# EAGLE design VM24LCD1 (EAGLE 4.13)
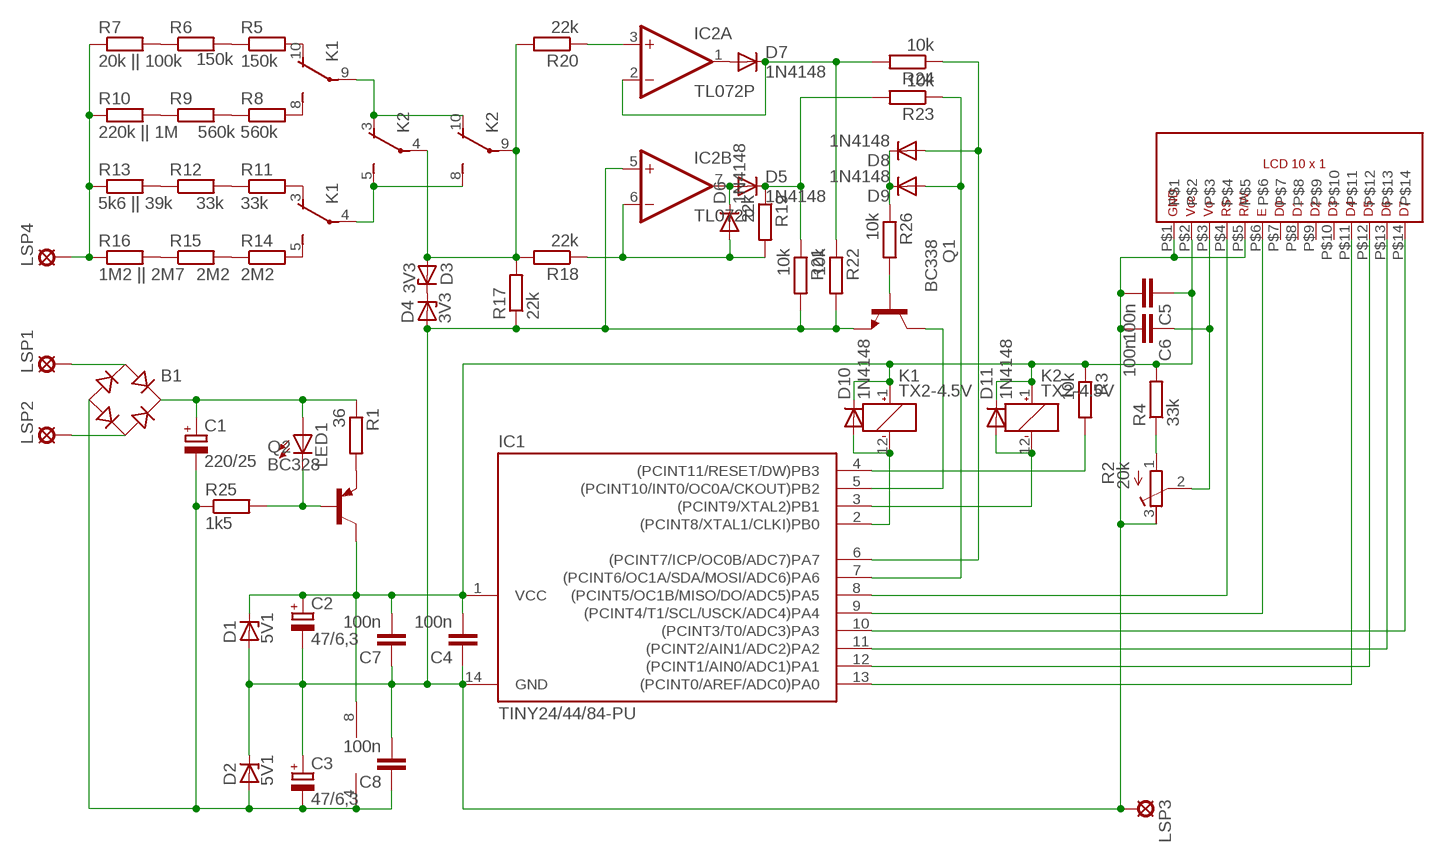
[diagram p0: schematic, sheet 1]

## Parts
B1  B-DIL  [B-DIL]
C1  220/25  CPOL-EUE5-6  [E5-6]
C2  47/6,3  CPOL-EUE5-6  [E5-6]
C3  47/6,3  CPOL-EUE5-6  [E5-6]
C4  100n  C-EUC1206  [C1206]
C5  100n  C-EUC0805K  [C0805K]
C6  100n  C-EUC0805K  [C0805K]
C7  100n  C-EUC1206  [C1206]
C8  100n  C-EUC1206  [C1206]
D1  5V1  ZENER-DIODESMB  [SMB]
D2  5V1  ZENER-DIODESMB  [SMB]
D3  3V3  ZENER-DIODEZD-2.5  [ZDIO-2.5]
D4  3V3  ZENER-DIODEZD-2.5  [ZDIO-2.5]
D5  1N4148  DIODE-D-2.5  [D-2.5]
D6  1N4148  DIODE-D-2.5  [D-2.5]
D7  1N4148  DIODE-D-2.5  [D-2.5]
D8  1N4148  DIODE-D-2.5  [D-2.5]
D9  1N4148  DIODE-D-5  [D-5]
D10  1N4148  DIODE-MINIMELF  [MINIMELF]
D11  1N4148  DIODE-MINIMELF  [MINIMELF]
IC1  TINY24/44/84-PU  [DIL14]
IC2  TL072P  [DIL08]
K1  TX2-4.5V  [TX2]
K2  TX2-4.5V  [TX2]
LED1  LEDSMT1206  [1206]
LSP1  LSP10  [LSP10]
LSP2  LSP10  [LSP10]
LSP3  LSP10  [LSP10]
LSP4  LSP10  [LSP10]
Q1  BC338  [TO92-EBC]
Q2  BC328  [TO92-EBC]
R1  36  R-EU_0207/10  [0207/10]
R2  20k  R-TRIMM4G/J  [RTRIM4G/J]
R3  10k  R-EU_M0805  [M0805]
R4  33k  R-EU_M0805  [M0805]
R5  150k  R-EU_0207/10  [0207/10]
R6  150k  R-EU_0207/10  [0207/10]
R7  20k || 100k  R-EU_0207/10  [0207/10]
R8  560k  R-EU_0207/10  [0207/10]
R9  560k  R-EU_0207/10  [0207/10]
R10  220k || 1M  R-EU_0207/10  [0207/10]
R11  33k  R-EU_0207/10  [0207/10]
R12  33k  R-EU_0207/10  [0207/10]
R13  5k6 || 39k  R-EU_0207/10  [0207/10]
R14  2M2  R-EU_0207/10  [0207/10]
R15  2M2  R-EU_0207/10  [0207/10]
R16  1M2 || 2M7  R-EU_0207/10  [0207/10]
R17  22k  R-EU_0204/7  [0204/7]
R18  22k  R-EU_0204/7  [0204/7]
R19  22k  R-EU_0204/5  [0204/5]
R20  22k  R-EU_0204/7  [0204/7]
R21  10k  R-EU_M0805  [M0805]
R22  10k  R-EU_M0805  [M0805]
R23  10k  R-EU_0204/7  [0204/7]
R24  10k  R-EU_0204/5  [0204/5]
R25  1k5  R-EU_MELF0204W  [MINI_MELF-0204W]
R26  10k  R-EU_MELF0102W  [MINI_MELF-0102W]
U$1  LCD10X1P  [LCD10X1P]

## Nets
N$1: B1.+ C1.+ LED1.A R1.1
N$2: C2.+ C4.2 C5.1 C7.2 D1.C D10.C D11.C IC1.1(VCC) IC2.8(P:V+) K1.1(_:+) K2.1(_:+) Q2.C R3.1 R4.2 U$1.P$2
N$3: C2.- C3.+ C4.1 C5.2 C6.2 C7.1 C8.2 D1.A D2.C D4.A IC1.14(GND) IC2.5(B:+IN) LSP3.MP Q1.E R2.3(A) R17.1 R21.2 R22.2 U$1.P$1 U$1.P$5
N$4: B1.- C1.- C3.- C8.1 D2.A IC2.4(P:V-) R25.1
N$5: IC1.10((PCINT3/T0/ADC3)PA3) U$1.P$14
N$6: IC1.11((PCINT2/AIN1/ADC2)PA2) U$1.P$13
N$7: IC1.12((PCINT1/AIN0/ADC1)PA1) U$1.P$12
N$8: IC1.13((PCINT0/AREF/ADC0)PA0) U$1.P$11
N$9: IC1.9((PCINT4/T1/SCL/USCK/ADC4)PA4) U$1.P$6
N$10: IC1.8((PCINT5/OC1B/MISO/DO/ADC5)PA5) U$1.P$4
N$11: R2.1(E) R4.1
N$12: C6.1 R2.2(S) U$1.P$3
N$13: D10.A IC1.2((PCINT8/XTAL1/CLKI)PB0) K1.12(_:-)
N$14: IC1.4((PCINT11/RESET/DW)PB3) R3.2
N$15: D11.A IC1.3((PCINT9/XTAL2)PB1) K2.12(_:-)
N$16: D3.A K2.4(1:P) K2.9(2:P) R17.2 R18.2 R20.2
N$17: K1.4(1:P) K2.5(1:S) K2.8(2:S)
N$18: K1.9(2:P) K2.3(1:O) K2.10(2:O)
N$19: K1.10(2:O) R5.2
N$20: R5.1 R6.2
N$21: R6.1 R7.2
N$22: K1.8(2:S) R8.2
N$23: R8.1 R9.2
N$24: R9.1 R10.2
N$25: K1.3(1:O) R11.2
N$26: R11.1 R12.2
N$27: R12.1 R13.2
N$28: K1.5(1:S) R14.2
N$29: R14.1 R15.2
N$30: R15.1 R16.2
N$31: LSP4.MP R7.1 R10.1 R13.1 R16.1
N$40: D3.C D4.C
N$41: D5.A D6.C IC2.7(B:OUT)
N$42: D7.A IC2.1(A:OUT)
N$43: D5.C R19.1 R21.1 R23.2
N$44: D6.A IC2.6(B:-IN) R18.1 R19.2
N$45: B1.AC1 LSP1.MP
N$46: IC2.3(A:+IN) R20.1
N$47: D7.C IC2.2(A:-IN) R22.1 R24.2
N$48: IC1.5((PCINT10/INT0/OC0A/CKOUT)PB2) Q1.C
N$49: D8.C D9.C R26.1
N$50: D8.A IC1.6((PCINT7/ICP/OC0B/ADC7)PA7) R24.1
N$51: D9.A IC1.7((PCINT6/OC1A/SDA/MOSI/ADC6)PA6) R23.1
N$52: B1.AC2 LSP2.MP
N$61: Q2.E R1.2
N$62: LED1.C Q2.B R25.2
N$66: Q1.B R26.2
Unconnected: U$1.P$7 U$1.P$8 U$1.P$9 U$1.P$10

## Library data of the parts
B1 = rectifier:B-DIL: RECTIFIER
C1-C3 = rcl:CPOL-EU: POLARIZED CAPACITOR, European symbol
C4-C8 = rcl:C-EU: CAPACITOR, European symbol
D1-D4 = diode:ZENER-DIODE: Z-Diode
D5-D11 = diode:DIODE-: DIODE
IC1 = avr-4:TINY24/44/84
IC2 = linear:TL072: OP AMP
K1 K2 = relay:TX2?-*: 2 AMP. HIGH CAPACITY RELAY NAiS WITH HIGH SURGE VOLTAGE & HIGH BREAKDOWN VOLTAGE Source: http://www.mew-europe.com/.. en_ds_61022_0001.pdf
LED1 = led:LED: LED
LSP1-LSP4 = solpad:LSP10: SOLDER PAD
Q1 = transistor-npn:BC338*: NPN Transistor
Q2 = transistor-pnp:BC328*: PNP Transistror
R1 R3-R26 = rcl:R-EU_: RESISTOR, European symbol
R2 = rcl:R-TRIMM: Trimm resistor
U$1 = meine:LCD10X1P

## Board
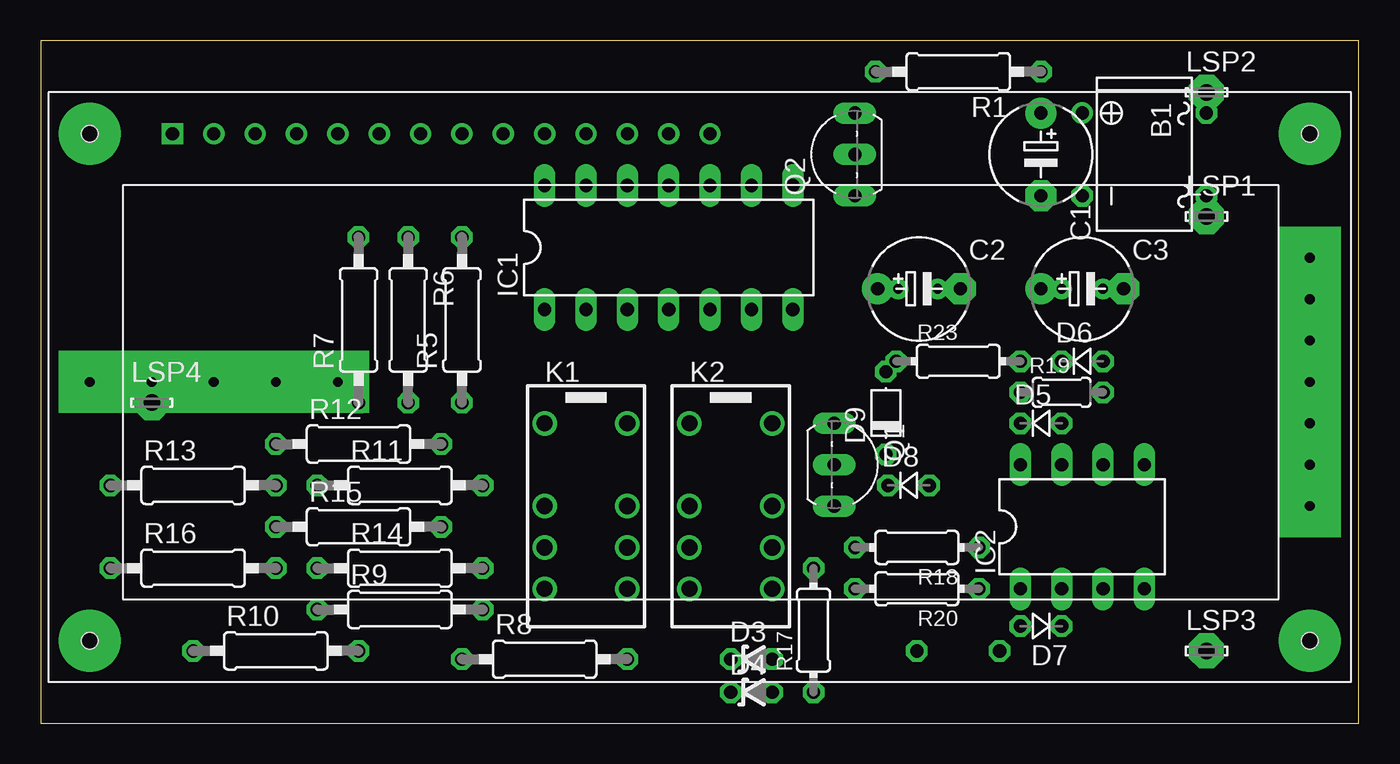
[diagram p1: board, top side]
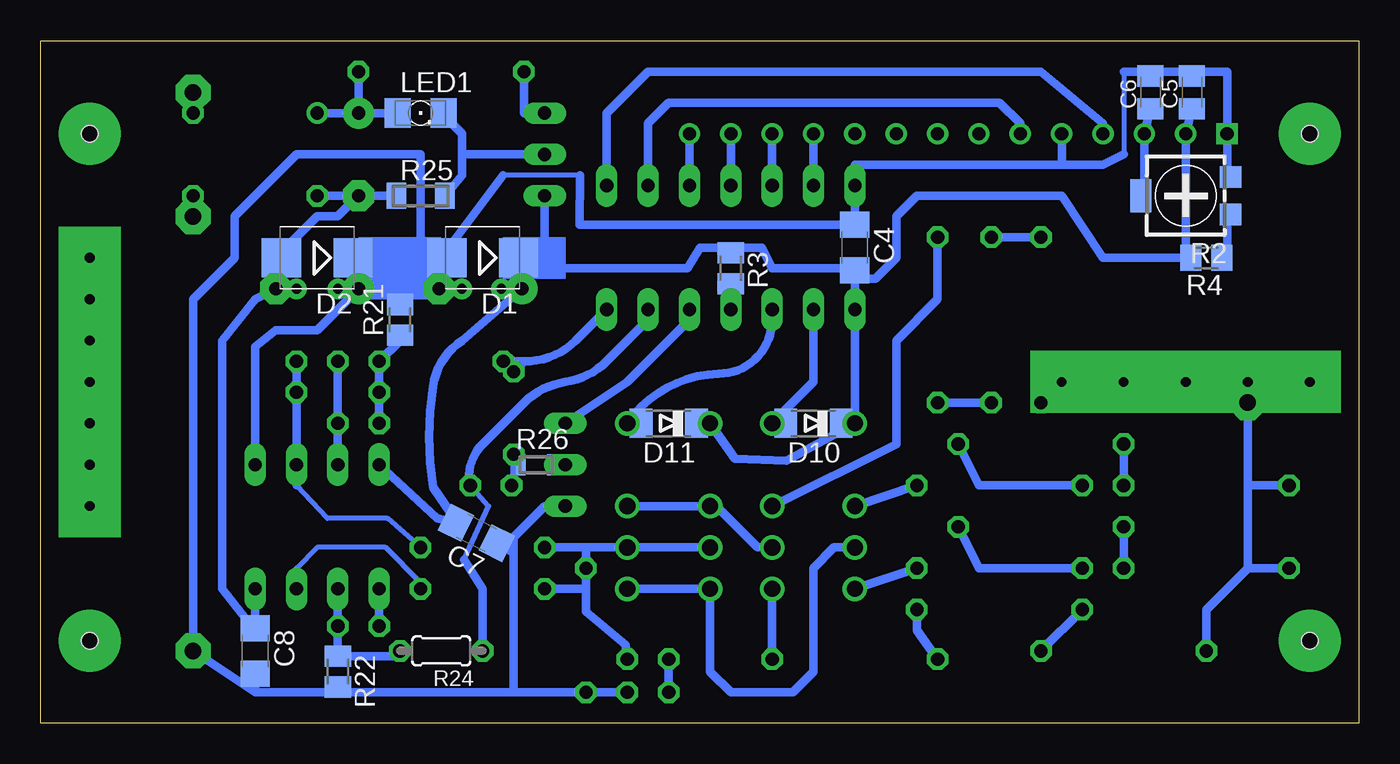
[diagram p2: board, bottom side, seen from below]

Size 80.95 x 41.9 mm. Coordinates in mm from the lower left corner, seen from the top.
Outline: 0,0 80.95,0 80.95,41.9 0,41.9 0,0
Copper layers (1*16): Top 0.035mm / dielectric 1.5mm / Bottom 0.035mm
Design rules "default": minimum track width 10mil, minimum drill 24mil, track to track 8mil, track to pad 8mil, pad to pad 8mil, via to via 8mil, smd to smd 0mil, copper to edge 40mil, drill to drill 8mil, minimum pad ring 10mil, minimum via ring 8mil, stop-mask expansion 4mil, vias tented up to drill 0mil, thermal gap 10mil

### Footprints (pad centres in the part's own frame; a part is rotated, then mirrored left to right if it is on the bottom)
B-DIL = drill 0.813 round: + -2.54,-3.81 | drill 0.813 octagon: - 2.54,-3.81; AC1 2.54,3.81; AC2 -2.54,3.81
E5-6 = drill 0.813 pad 1.905 round: + -2.54,0 | drill 0.813 pad 1.905 octagon: - 2.54,0
C1206 = smd 1.6 x 1.8: 1 -1.4,0; 2 1.4,0
C0805K = smd 1.3 x 1.6: 1 -1,0; 2 1,0
SMB = smd 2.4 x 2.4: A 2.2,0; C -2.2,0
ZDIO-2.5 = drill 0.813 octagon: A 1.27,0; C -1.27,0
D-2.5 = drill 0.813 octagon: A 1.27,0; C -1.27,0
D-5 = drill 0.813 octagon: A 2.54,0; C -2.54,0
MINIMELF = smd 1.4 x 1.8: A 1.7,0; C -1.7,0
DIL14 = drill 0.813 long: 1 -7.62,-3.81; 2 -5.08,-3.81; 3 -2.54,-3.81; 4 0,-3.81; 5 2.54,-3.81; 6 5.08,-3.81; 7 7.62,-3.81; 8 7.62,3.81; 9 5.08,3.81; 10 2.54,3.81; 11 0,3.81; 12 -2.54,3.81; 13 -5.08,3.81; 14 -7.62,3.81
DIL08 = drill 0.813 long: 1 -3.81,-3.81; 2 -1.27,-3.81; 3 1.27,-3.81; 4 3.81,-3.81; 5 3.81,3.81; 6 1.27,3.81; 7 -1.27,3.81; 8 -3.81,3.81
TX2 = drill 1 round: 1 -5.08,-2.54; 3 0,-2.54; 4 2.54,-2.54; 5 5.08,-2.54; 8 5.08,2.54; 9 2.54,2.54; 10 0,2.54; 12 -5.08,2.54
1206 = smd 1.6 x 1.803: A -1.422,0; C 1.422,0
LSP10 = drill 1.016 pad 2.159 octagon: MP 0,0
TO92-EBC = drill 0.813 long: B 0,-1.27; C -2.54,-1.27; E 2.54,-1.27
0207/10 = drill 0.813 octagon: 1 -5.08,0; 2 5.08,0
RTRIM4G/J = smd 1.3 x 1.3: 1 -1.15,-2.75; 3 1.15,-2.75 | smd 2 x 1.3: 2 0,2.75
M0805 = smd 1.3 x 1.6: 1 -0.95,0; 2 0.95,0
0204/7 = drill 0.813 octagon: 1 -3.81,0; 2 3.81,0
0204/5 = drill 0.813 octagon: 1 -2.54,0; 2 2.54,0
MINI_MELF-0204W = smd 1.2 x 1.6: 1 -1.5,0; 2 1.5,0
MINI_MELF-0102W = smd 0.6 x 1.3: 1 -0.95,0; 2 0.95,0
LCD10X1P = drill 0.8 square: P$1 7.62,33.02 | drill 0.8 round: P$2 10.16,33.02; P$3 12.7,33.02; P$4 15.24,33.02; P$5 17.78,33.02; P$6 20.32,33.02; P$7 22.86,33.02; P$8 25.4,33.02; P$9 27.94,33.02; P$10 30.48,33.02; P$11 33.02,33.02; P$12 35.56,33.02; P$13 38.1,33.02; P$14 40.64,33.02 | hole 1: 2.54,1.905; 2.54,33.02; 77.47,33.02; 77.47,1.905

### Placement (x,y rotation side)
B1  67.78,34.92 270 top
C1  61.43,34.92 270 top
C2  53.94,26.66 0 top
C3  63.97,26.66 0 top
C4  30.95,29.2 270 bottom
C5  10.25,38.73 90 bottom
C6  12.79,38.73 90 bottom
C7  54.19,11.68 153.5 bottom
C8  67.78,4.44 270 bottom
D1  53.81,28.57 180 bottom
D2  63.97,28.57 180 bottom
D3  43.65,3.93 0 top
D4  43.65,1.9 0 top
D5  61.43,18.41 0 top
D6  63.97,22.22 0 top
D7  61.43,5.96 180 top
D8  53.3,14.6 0 top
D9  51.91,19.04 90 top
D10  33.49,18.41 180 bottom
D11  42.38,18.41 180 bottom
IC1  38.57,29.2 0 top
IC2  63.97,12.06 0 top
K1  33.49,13.33 270 top
K2  42.38,13.33 270 top
LED1  57.62,37.46 0 bottom
LSP1  71.59,31.11 0 top
LSP2  71.59,38.73 0 top
LSP3  71.59,4.44 0 top
LSP4  6.82,19.68 0 top
Q1  50,15.87 270 top
Q2  48.73,34.92 90 top
R1  56.35,40 180 top
R2  10.63,32.38 90 bottom
R3  38.57,27.93 270 bottom
R4  9.36,28.57 180 bottom
R5  25.87,24.76 90 top
R6  22.57,24.76 270 top
R7  19.52,24.76 90 top
R8  30.95,3.93 0 top
R9  22.06,6.98 0 top
R10  14.44,4.44 0 top
R11  22.06,14.6 0 top
R12  19.52,17.14 0 top
R13  9.36,14.6 0 top
R14  22.06,9.52 0 top
R15  19.52,12.06 0 top
R16  9.36,9.52 0 top
R17  47.46,5.71 90 top
R18  53.81,10.79 180 top
R19  62.7,20.31 0 top
R20  53.81,8.25 180 top
R21  58.89,24.76 90 bottom
R22  62.7,3.17 270 bottom
R23  56.35,22.22 0 top
R24  56.35,4.44 180 bottom
R25  57.62,32.38 0 bottom
R26  50.51,15.87 0 bottom
U$1  0.47,3.17 0 top

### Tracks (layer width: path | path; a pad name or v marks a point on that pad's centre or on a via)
N$1
  Bottom 0.508: C1.+ R1.1 | C1.+ B1.+ | LED1.A C1.+
N$2
  Bottom 0.406: K1.1 D10.C | K2.1 D11.C
  Bottom 0.508: C5.1 U$1.P$2 10.63,28.57 | R4.2 10.63,28.57 | 30.95,27.3 IC1.1 K1.1 35.14,16.12 38.32,16.25 K2.1 | 30.95,27.3 C4.2 30.95,27.93 36.03,27.93 36.66,29.2 38.57,29.2 | 10.63,28.57 15.71,28.57 18.25,32.38 27.14,32.38 28.41,31.11 28.41,28.57 29.68,27.3 30.95,27.3 | 38.57,29.2 40.48,29.2 41.24,27.93 51.4,27.93 | 38.57,29.2 R3.1 | 51.4,27.93 D1.C | 51.4,27.93 51.35,27.29 | 51.35,27.29 C2.+ 55.08,23.49 arc-48 56.86,20.7 arc-17 56.86,14.47 55.44,12.42 C7.2 55.46,12.31 56.6,12.57 IC2.8 | 51.35,27.29 51.28,27.29 50,28.57 Q2.C
N$3
  Bottom 0.305: 14.44,40 14.44,34.92 | 47.84,33.65 52.54,33.65
  Bottom 0.508: 30.95,33.65 30.95,34.29 18.25,34.29 | 30.95,33.65 IC1.14 | 18.25,34.29 U$1.P$5 | 18.25,34.29 15.71,34.29 14.44,34.92 | 10.63,40 8.09,40 U$1.P$1 8.09,33.53 R2.3 | 10.63,40 13.17,40 | 13.17,40 14.44,40 | 10.63,40 C5.2 | 13.17,40 C6.2 | 30.95,33.65 C4.1 47.84,30.61 47.84,33.65 | 52.54,33.65 56.35,28.57 D1.A 55.71,28.57 56.35,27.93 C2.- | D2.C 61.43,28.57 C3.+ | C2.- C3.+ | C3.+ 63.97,24.12 66.51,24.12 67.78,23.11 IC2.5 | C2.- 57.62,29.84 57.62,34.92 65.24,34.92 69.05,31.11 69.05,28.57 71.59,26.03 LSP3.MP 67.78,1.9 | D4.A R17.1 51.91,1.9 | 67.78,1.9 62.7,1.9 | 62.7,1.9 51.91,1.9 | 51.91,1.9 51.91,10.54 | 51.91,10.54 51.91,11.43 50,13.33 Q1.E | 51.91,10.54 52.03,10.54 C7.1 | 67.78,1.9 C8.2 | R21.2 58.89,26.03 58.25,26.66 C2.- | 62.7,1.9 R22.2
N$4
  Bottom 0.508: C1.- B1.- | C1.- 62.7,31.11 63.97,31.11 66.17,28.91 D2.A 66.51,28.57 C3.- 67.78,26.03 69.81,23.49 69.81,8.25 67.91,5.84 C8.1 | C8.1 67.78,5.71 | C8.1 IC2.4 | C1.- R25.1
N$5
  Bottom 0.508: IC1.10 U$1.P$14
N$6
  Bottom 0.508: IC1.11 U$1.P$13
N$7
  Bottom 0.508: IC1.12 U$1.P$12
N$8
  Bottom 0.508: IC1.13 U$1.P$11
N$9
  Bottom 0.508: IC1.9 43.65,36.83 42.38,38.1 22.06,38.1 20.79,36.83 U$1.P$6
N$10
  Bottom 0.508: IC1.8 46.19,37.46 43.65,40 19.52,40 15.71,36.83 U$1.P$4
N$11
  Bottom 0.508: R4.1 8.09,28.57 8.09,31.23 R2.1
N$12
  Bottom 0.508: C6.1 U$1.P$3 13.17,32.38 R2.2
N$13
  Bottom 0.406: D10.A K1.12
  Bottom 0.508: IC1.2 33.49,20.95 K1.12
N$14
  Bottom 0.508: IC1.4 R3.2
N$15
  Bottom 0.406: K2.12 D11.A
  Bottom 0.508: IC1.3 36.03,24.76 arc90 39.33,21.46 arc-53 K2.12
N$16
  Bottom 0.508: K2.4 K2.9 47.46,10.79 | 47.46,8.25 47.46,6.85 45.05,4.82 D3.A | 47.46,8.25 R17.2 47.46,10.79 | 47.46,10.79 R18.2 | 47.46,8.25 R20.2
N$17
  Bottom 0.508: K1.4 32.22,10.79 33.49,9.52 33.49,3.17 34.76,1.9 38.57,1.9 39.84,3.17 K2.5 K2.8
N$18
  Bottom 0.508: K2.10 K2.3 39.46,13.33 36.92,10.79 K1.9
N$19
  Bottom 0.508: K1.10 28.41,17.14 28.41,23.49 25.87,26.03 R5.2
N$20
  Bottom 0.508: R6.2 R5.1
N$21
  Bottom 0.508: R7.2 R6.1
N$22
  Bottom 0.508: R8.2 K1.8
N$23
  Bottom 0.508: R9.2 27.14,5.71 R8.1
N$24
  Bottom 0.508: R10.2 R9.1
N$25
  Bottom 0.508: R11.2 K1.3
N$26
  Bottom 0.508: R11.1 23.33,14.6 R12.2
N$27
  Bottom 0.508: R13.2 R12.1
N$28
  Bottom 0.508: R14.2 K1.5
N$29
  Bottom 0.508: R14.1 23.33,9.52 R15.2
N$30
  Bottom 0.508: R16.2 R15.1
N$31
  Bottom 0.508: R10.1 9.36,6.98 6.82,9.52 | R16.1 6.82,9.52 | R7.1 LSP4.MP 6.82,14.6 | 6.82,9.52 6.82,14.6 | 6.82,14.6 R13.1
N$32  (via drill 0.6 pad 3.81)
  other vias: 6.82,20.95
N$33  (via drill 0.6 pad 3.81)
  other vias: 10.63,20.95
N$34  (via drill 0.6 pad 3.81)
  other vias: 14.44,20.95
N$35  (via drill 0.6 pad 3.81)
  other vias: 18.25,20.95
N$36  (via drill 0.6 pad 3.81)
  other vias: 3.01,36.19
N$37  (via drill 0.6 pad 3.81)
  other vias: 3.01,5.08
N$38  (via drill 0.6 pad 3.81)
  other vias: 77.94,5.08
N$39  (via drill 0.6 pad 3.81)
  other vias: 77.94,36.19
N$40
  Bottom 0.508: D4.C D3.C
N$41
  Bottom 0.508: D6.C D5.A IC2.7
N$42
  Bottom 0.508: D7.A IC2.1
N$43
  Bottom 0.508: D5.C 60.16,20.19 60.29,20.31 R19.1 R23.2 58.89,23.49 R21.1
N$44
  Bottom 0.305: R18.1 59.65,12.57 63.34,12.57 65.24,14.6
  Bottom 0.508: D6.A R19.2 IC2.6 65.24,14.6
N$45
  Bottom 0.508: LSP1.MP B1.AC1
N$46
  Bottom 0.305: R20.1 57.62,8.63 59.78,10.79 63.97,10.79 65.24,9.52 IC2.3
N$47
  Bottom 0.508: R24.2 arc90 59.21,4.12 R22.1 D7.C | D7.C 62.7,6.09 | 62.7,8.38 IC2.2 D7.C
N$48
  Bottom 0.508: IC1.5 41.11,24.76 44.92,20.95 Q1.C
N$49
  Bottom 0.406: 51.91,15.87 R26.1 | 51.91,15.87 D9.C | 51.91,15.87 51.91,15.36 D8.C
N$50
  Bottom 0.305: D8.A 53.43,13.33 54.95,10.03
  Bottom 0.508: IC1.6 43.65,24.76 46.19,22.22 arc37 48.73,20.95 arc-37 51.27,19.68 53.81,17.14 arc-58 54.57,14.47 D8.A | 54.95,10.03 53.81,8.25 R24.1
N$51
  Bottom 0.508: 51.27,22.22 R23.1 | 51.27,22.22 D9.A | IC1.7 48.09,23.49 arc46 51.27,22.22
N$52
  Bottom 0.508: B1.AC2 LSP2.MP
N$53  (via drill 0.6 pad 1.27)
  other vias: 52.67,26.66
N$54  (via drill 0.6 pad 3.81)
  other vias: 77.94,13.33
N$55  (via drill 0.6 pad 3.81)
  other vias: 77.94,18.41
N$56  (via drill 0.6 pad 3.81)
  other vias: 77.94,23.49
N$57  (via drill 0.6 pad 3.81)
  other vias: 77.94,28.57
N$58  (via drill 0.6 pad 1.27)
  other vias: 55.08,26.66
N$59  (via drill 0.6 pad 1.27)
  other vias: 62.7,26.66
N$60  (via drill 0.6 pad 1.27)
  other vias: 65.24,26.66
N$61
  Bottom 0.508: R1.2 51.27,37.46 Q2.E
N$62
  Bottom 0.508: R25.2 55.08,33.65 55.08,34.92 | LED1.C 56.35,37.46 55.08,36.19 55.08,34.92 | Q2.B 55.08,34.92
N$63  (via drill 0.6 pad 3.81)
  other vias: 77.94,26.03
N$64  (via drill 0.6 pad 3.81)
  other vias: 77.94,20.95
N$65  (via drill 0.6 pad 3.81)
  other vias: 77.94,15.87
N$66
  Bottom 0.406: R26.2 Q1.B
N$67  (via drill 0.6 pad 3.81)
  other vias: 3.01,20.95
(copper drawn outside any net)
  shapes: Bottom area x2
